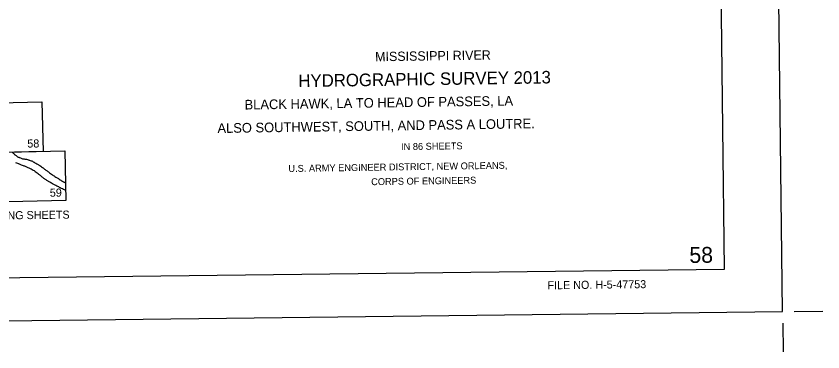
# Model space of a CAD drawing. Extents: x 3694830 to 3732949, y 415201 to 440970.
# Drawn here: x 3721259 to 3732949, y 415638 to 420497 of the extents above; entities that cross this region are included whole.
import ezdxf

# ---------------------------------------------------------------- set-up
doc = ezdxf.new("R2010")
doc.units = 0
for name, color, linetype in [('G-ANNO-NPLT', 7, 'Continuous'), ('V-ANNO-DIMS', 7, 'Continuous'), ('V-ANNO-NPLT', 7, 'Continuous'), ('V-ANNO-SYMB', 7, 'Continuous'), ('V-ANNO-TEXT', 7, 'Continuous')]:
    doc.layers.add(name, color=color, linetype=linetype)

msp = doc.modelspace()

# ---------------------------------------------------------------- linework, layer by layer
at = {"layer": 'G-ANNO-NPLT'}
msp.add_lwpolyline([(3695701, 415784), (3732365, 416222), (3732077, 440387), (3695413, 439949)], close=True, dxfattribs=at)
at = {"layer": 'V-ANNO-DIMS'}
for p, q in [((3732532, 416224), (3732949, 416229)), ((3732367, 416055), (3732372, 415638))]:
    msp.add_line(p, q, dxfattribs=at)
at = {"layer": 'V-ANNO-NPLT'}
for points in [[(3720395, 418510), (3720379, 419228), (3721632, 419258), (3721650, 418540)], [(3721650, 418540), (3720395, 418510)], [(3720726, 417799), (3720709, 418517), (3721963, 418548), (3721981, 417830)], [(3721981, 417830), (3720726, 417799)]]:
    msp.add_lwpolyline(points, dxfattribs=at)
for points in [[(3721207, 418522), (3721224, 418507), (3721241, 418491), (3721248, 418484), (3721271, 418471), (3721290, 418455), (3721295, 418454), (3721302, 418453), (3721310, 418451), (3721352, 418434)], [(3721352, 418434), (3721359, 418432), (3721365, 418432), (3721368, 418432), (3721384, 418428), (3721389, 418428), (3721393, 418428), (3721398, 418429), (3721403, 418429), (3721411, 418426), (3721434, 418418), (3721440, 418418), (3721449, 418414), (3721478, 418403)], [(3721478, 418403), (3721486, 418401), (3721508, 418389), (3721521, 418382), (3721543, 418369), (3721576, 418349), (3721584, 418346), (3721615, 418325)], [(3721249, 418379), (3721280, 418367), (3721292, 418363), (3721314, 418354), (3721348, 418340), (3721392, 418324), (3721428, 418308)], [(3721428, 418308), (3721460, 418293), (3721492, 418277), (3721520, 418261)], [(3721615, 418325), (3721642, 418307), (3721679, 418277), (3721701, 418262), (3721734, 418238), (3721755, 418220)], [(3721520, 418261), (3721548, 418240), (3721576, 418218), (3721607, 418193), (3721633, 418171)], [(3721633, 418171), (3721664, 418147), (3721698, 418125), (3721734, 418104), (3721760, 418089)], [(3721755, 418220), (3721785, 418199), (3721810, 418184), (3721832, 418168), (3721871, 418145)], [(3721760, 418089), (3721784, 418075), (3721819, 418056), (3721848, 418041), (3721897, 418017), (3721930, 418001), (3721957, 417988), (3721977, 417980)], [(3721871, 418145), (3721897, 418128), (3721916, 418115), (3721944, 418101), (3721974, 418085)]]:
    msp.add_spline(points, degree=3, dxfattribs=at)
at = {"layer": 'V-ANNO-SYMB'}
msp.add_lwpolyline([(3698444, 416442), (3731525, 416837), (3731251, 439752), (3698171, 439357), (3698444, 416442)], dxfattribs=at)

# ---------------------------------------------------------------- texts
at = {"layer": 'V-ANNO-NPLT'}
for s, height, p in [('58', 117, (3721421, 418594)), ('59', 117, (3721747, 417883)), ('INDEX TO ADJOINING SHEETS', 116.66, (3719738, 417539))]:
    msp.add_text(s, height=height, rotation=0.6833, dxfattribs=at).set_placement(p)
at = {"layer": 'V-ANNO-TEXT'}
for s, height, rotation, p in [('MISSISSIPPI RIVER', 135, 0.8591, (3726462, 419843)), ('HYDROGRAPHIC SURVEY 2013', 181.7, 0.8591, (3725350, 419469)), ('BLACK HAWK, LA TO HEAD OF PASSES, LA', 140, 0.8591, (3724570, 419145)), ('ALSO SOUTHWEST, SOUTH, AND PASS A LOUTRE.', 140, 0.8591, (3724177, 418805)), ('IN 86 SHEETS', 100, 0.8591, (3726837, 418557)), ('U.S. ARMY ENGINEER DISTRICT, NEW ORLEANS,', 100, 0.8591, (3725205, 418241)), ('CORPS OF ENGINEERS', 100, 0.8591, (3726404, 418050)), ('58', 230, 0.6833, (3731016, 416924)), ('FILE NO. H-5-47753', 116.66, 0.6834, (3728959, 416543))]:
    msp.add_text(s, height=height, rotation=rotation, dxfattribs=at).set_placement(p)

doc.saveas('drawing.dxf')
